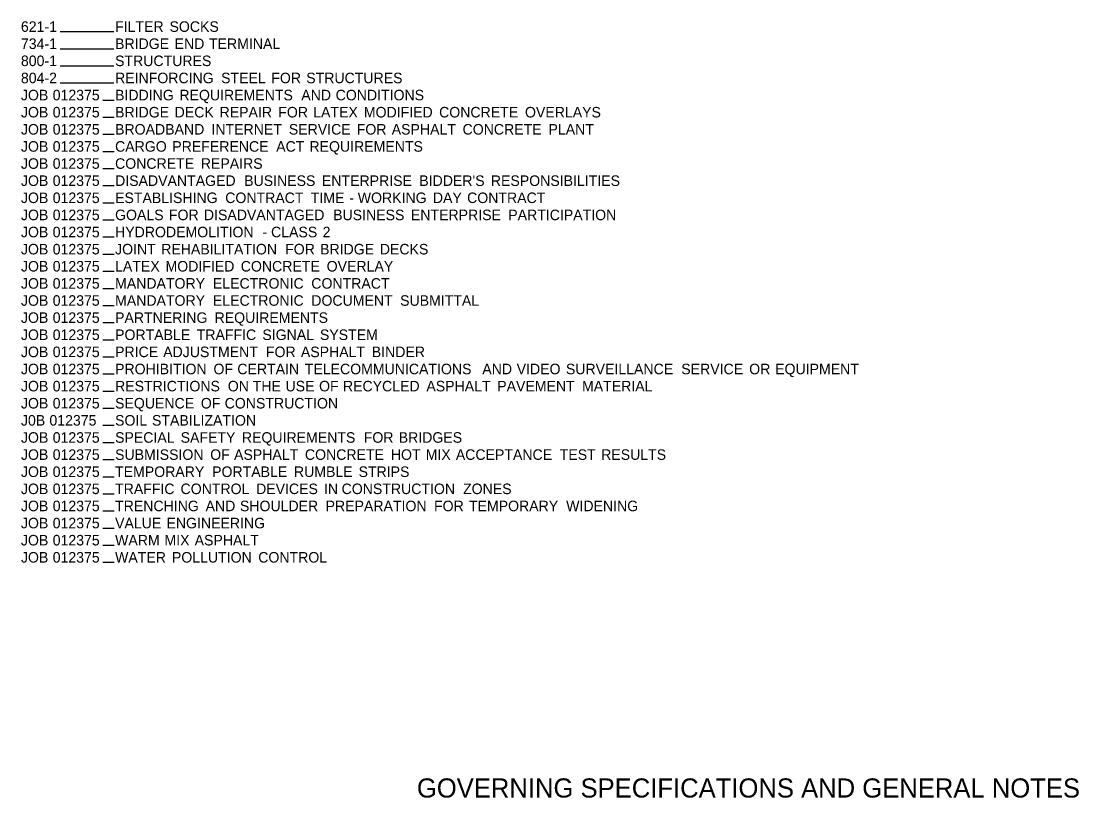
# Model space of a CAD drawing. Extents: x 1930579 to 1932220, y 596452 to 599479.
# Drawn here: x 1931525 to 1932188, y 598494 to 598981 of the extents above; entities that cross this region are included whole.
import ezdxf

# ---------------------------------------------------------------- set-up
doc = ezdxf.new("R2010")
doc.units = 0
doc.layers.add('Default', color=7, linetype='Continuous')
doc.layers.add('R_Border', color=7, linetype='Continuous')

msp = doc.modelspace()

# ---------------------------------------------------------------- linework, layer by layer
at = {"layer": 'R_Border'}
for p, q in [((1931549.9, 598974.32), (1931583.53, 598974.32)), ((1931549.9, 598963.59), (1931583.53, 598963.59)), ((1931549.9, 598952.87), (1931583.53, 598952.87)), ((1931549.9, 598942.14), (1931583.53, 598942.14)), ((1931576.59, 598931.42), (1931583.8, 598931.42)), ((1931576.59, 598920.69), (1931583.8, 598920.69)), ((1931576.59, 598909.97), (1931583.8, 598909.97)), ((1931576.59, 598899.24), (1931583.8, 598899.24)), ((1931576.59, 598888.52), (1931583.8, 598888.52)), ((1931576.59, 598877.79), (1931583.8, 598877.79)), ((1931576.59, 598867.07), (1931583.8, 598867.07)), ((1931576.59, 598856.34), (1931583.8, 598856.34)), ((1931576.59, 598845.62), (1931583.8, 598845.62)), ((1931576.59, 598834.89), (1931583.8, 598834.89)), ((1931576.59, 598824.17), (1931583.8, 598824.17)), ((1931576.59, 598813.44), (1931583.8, 598813.44)), ((1931576.59, 598802.72), (1931583.8, 598802.72)), ((1931576.59, 598791.99), (1931583.8, 598791.99)), ((1931576.59, 598781.27), (1931583.8, 598781.27)), ((1931576.59, 598770.54), (1931583.8, 598770.54)), ((1931576.59, 598759.82), (1931583.8, 598759.82)), ((1931576.59, 598749.09), (1931583.8, 598749.09)), ((1931576.59, 598738.37), (1931583.8, 598738.37)), ((1931576.59, 598727.64), (1931583.8, 598727.64)), ((1931576.59, 598716.92), (1931583.8, 598716.92)), ((1931576.59, 598706.19), (1931583.8, 598706.19)), ((1931576.59, 598695.47), (1931583.8, 598695.47)), ((1931576.59, 598684.74), (1931583.8, 598684.74)), ((1931576.59, 598674.02), (1931583.8, 598674.02)), ((1931576.59, 598663.29), (1931583.8, 598663.29)), ((1931576.59, 598652.57), (1931583.8, 598652.57)), ((1931576.59, 598641.84), (1931583.8, 598641.84))]:
    msp.add_line(p, q, dxfattribs=at)

# ---------------------------------------------------------------- texts
at = {"layer": 'Default'}
for s, p in [('621-1', (1931525.34, 598974.13)), ('FILTER', (1931584.33, 598974.13)), (' SOCKS', (1931615.97, 598974.13)), ('734-1', (1931525.34, 598963.4)), ('BRIDGE', (1931584.33, 598963.4)), (' END', (1931619.19, 598963.4)), (' TERMINAL', (1931640.73, 598963.4)), ('800-1', (1931525.34, 598952.68)), ('STRUCTURES', (1931584.33, 598952.68)), ('804-2', (1931525.34, 598941.95)), ('REINFORCING', (1931584.33, 598941.95)), (' STEEL', (1931648.3, 598941.95)), (' FOR', (1931679.76, 598941.95)), (' STRUCTURES', (1931701.66, 598941.95)), ('JOB', (1931525.34, 598931.23)), (' 012375', (1931542.79, 598931.23)), ('BIDDING', (1931584.33, 598931.23)), (' REQUIREMENTS', (1931622.18, 598931.23)), (' AND', (1931698.55, 598931.23)), (' CONDITIONS', (1931720.09, 598931.23)), ('JOB', (1931525.34, 598920.5)), (' 012375', (1931542.79, 598920.5)), ('BRIDGE', (1931584.33, 598920.5)), (' DECK', (1931619.19, 598920.5)), (' REPAIR', (1931647.36, 598920.5)), (' FOR', (1931684.13, 598920.5)), (' LATEX', (1931706.03, 598920.5)), (' MODIFIED', (1931737.75, 598920.5)), (' CONCRETE', (1931784.9, 598920.5)), (' OVERLAYS', (1931838.72, 598920.5)), ('JOB', (1931525.34, 598909.78)), (' 012375', (1931542.79, 598909.78)), ('BROADBAND', (1931584.33, 598909.78)), (' INTERNET', (1931642.26, 598909.78)), (' SERVICE', (1931690.75, 598909.78)), (' FOR', (1931733.3, 598909.78)), (' ASPHALT', (1931755.21, 598909.78)), (' CONCRETE', (1931799.61, 598909.78)), (' PLANT', (1931853.43, 598909.78)), ('JOB', (1931525.34, 598899.05)), (' 012375', (1931542.79, 598899.05)), ('CARGO', (1931584.33, 598899.05)), (' PREFERENCE', (1931617.73, 598899.05)), (' ACT', (1931682.84, 598899.05)), (' REQUIREMENTS', (1931703.66, 598899.05)), ('JOB', (1931525.34, 598888.33)), (' 012375', (1931542.79, 598888.33)), ('CONCRETE', (1931584.33, 598888.33)), (' REPAIRS', (1931635.59, 598888.33)), ('JOB', (1931525.34, 598877.6)), (' 012375', (1931542.79, 598877.6)), ('DISADVANTAGED', (1931584.33, 598877.6)), (' BUSINESS', (1931662.76, 598877.6)), (' ENTERPRISE', (1931711.48, 598877.6)), (" BIDDER'S", (1931772.48, 598877.6)), (' RESPONSIBILITIES', (1931817.32, 598877.6)), ('JOB', (1931525.34, 598866.88)), (' 012375', (1931542.79, 598866.88)), ('ESTABLISHING', (1931584.33, 598866.88)), (' CONTRACT', (1931650.89, 598866.88)), (' TIME', (1931704.5, 598866.88)), (' WORKING', (1931733.93, 598866.88)), (' DAY', (1931781, 598866.88)), (' CONTRACT', (1931802.45, 598866.88)), (' -', (1931728.59, 598866.88)), ('JOB', (1931525.34, 598856.15)), (' 012375', (1931542.79, 598856.15)), ('GOALS', (1931584.33, 598856.15)), (' FOR', (1931615.62, 598856.15)), (' DISADVANTAGED', (1931637.52, 598856.15)), (' BUSINESS', (1931718.52, 598856.15)), (' ENTERPRISE', (1931767.24, 598856.15)), (' PARTICIPATION', (1931828.24, 598856.15)), ('JOB', (1931525.34, 598845.43)), (' 012375', (1931542.79, 598845.43)), ('HYDRODEMOLITION', (1931584.33, 598845.43)), (' CLASS', (1931679.6, 598845.43)), (' 2', (1931711.93, 598845.43)), (' -', (1931674.26, 598845.43)), ('JOB', (1931525.34, 598834.7)), (' 012375', (1931542.79, 598834.7)), ('JOINT', (1931584.33, 598834.7)), (' REHABILITATION', (1931610.78, 598834.7)), (' FOR', (1931688.43, 598834.7)), (' BRIDGE', (1931710.33, 598834.7)), (' DECKS', (1931747.76, 598834.7)), ('JOB', (1931525.34, 598823.98)), (' 012375', (1931542.79, 598823.98)), ('LATEX', (1931584.33, 598823.98)), (' MODIFIED', (1931613.48, 598823.98)), (' CONCRETE', (1931660.63, 598823.98)), (' OVERLAY', (1931714.46, 598823.98)), ('JOB', (1931525.34, 598813.25)), (' 012375', (1931542.79, 598813.25)), ('MANDATORY', (1931584.33, 598813.25)), (' ELECTRONIC', (1931643.18, 598813.25)), (' CONTRACT', (1931704.82, 598813.25)), ('JOB', (1931525.34, 598802.53)), (' 012375', (1931542.79, 598802.53)), ('MANDATORY', (1931584.33, 598802.53)), (' ELECTRONIC', (1931643.18, 598802.53)), (' DOCUMENT', (1931704.82, 598802.53)), (' SUBMITTAL', (1931760.47, 598802.53)), ('JOB', (1931525.34, 598791.8)), (' 012375', (1931542.79, 598791.8)), ('PARTNERING', (1931584.33, 598791.8)), (' REQUIREMENTS', (1931644.21, 598791.8)), ('JOB', (1931525.34, 598781.08)), (' 012375', (1931542.79, 598781.08)), ('PORTABLE', (1931584.33, 598781.08)), (' TRAFFIC', (1931633.04, 598781.08)), (' SIGNAL', (1931674.17, 598781.08)), (' SYSTEM', (1931710.22, 598781.08)), ('JOB', (1931525.34, 598770.35)), (' 012375', (1931542.79, 598770.35)), ('PRICE', (1931584.33, 598770.35)), (' ADJUSTMENT', (1931612.02, 598770.35)), (' FOR', (1931676.39, 598770.35)), (' ASPHALT', (1931698.3, 598770.35)), (' BINDER', (1931742.7, 598770.35)), ('JOB', (1931525.34, 598759.63)), (' 012375', (1931542.79, 598759.63)), ('PROHIBITION', (1931584.33, 598759.63)), (' OF', (1931643.52, 598759.63)), (' CERTAIN', (1931658.47, 598759.63)), (' TELECOMMUNICATIONS', (1931700.75, 598759.63)), (' AND', (1931811.97, 598759.63)), (' VIDEO', (1931833.51, 598759.63)), (' SURVEILLANCE', (1931864.35, 598759.63)), (' SERVICE', (1931936.64, 598759.63)), (' OR', (1931979.19, 598759.63)), (' EQUIPMENT', (1931995.46, 598759.63)), ('JOB', (1931525.34, 598748.9)), (' 012375', (1931542.79, 598748.9)), ('RESTRICTIONS', (1931584.33, 598748.9)), (' ON', (1931652.51, 598748.9)), (' THE', (1931668.14, 598748.9)), (' USE', (1931688.66, 598748.9)), (' OF', (1931709.69, 598748.9)), (' RECYCLED', (1931724.64, 598748.9)), (' ASPHALT', (1931776.93, 598748.9)), (' PAVEMENT', (1931821.33, 598748.9)), (' MATERIAL', (1931874.45, 598748.9)), ('JOB', (1931525.34, 598738.18)), (' 012375', (1931542.79, 598738.18)), ('SEQUENCE', (1931584.33, 598738.18)), (' OF', (1931635.6, 598738.18)), (' CONSTRUCTION', (1931650.54, 598738.18)), ('J0B', (1931525.34, 598727.45)), (' 012375', (1931540.74, 598727.45)), ('SOIL', (1931584.33, 598727.45)), (' STABILIZATION', (1931605.01, 598727.45)), ('JOB', (1931525.34, 598716.73)), (' 012375', (1931542.79, 598716.73)), ('SPECIAL', (1931584.33, 598716.73)), (' SAFETY', (1931622.96, 598716.73)), (' REQUIREMENTS', (1931661.32, 598716.73)), (' FOR', (1931737.7, 598716.73)), (' BRIDGES', (1931759.6, 598716.73)), ('JOB', (1931525.34, 598706)), (' 012375', (1931542.79, 598706)), ('SUBMISSION', (1931584.33, 598706)), (' OF', (1931641.48, 598706)), (' ASPHALT', (1931656.42, 598706)), (' CONCRETE', (1931700.83, 598706)), (' HOT', (1931754.65, 598706)), (' MIX', (1931776.49, 598706)), (' ACCEPTANCE', (1931795.39, 598706)), (' TEST', (1931860.49, 598706)), (' RESULTS', (1931886.44, 598706)), ('JOB', (1931525.34, 598695.28)), (' 012375', (1931542.79, 598695.28)), ('TEMPORARY', (1931584.33, 598695.28)), (' PORTABLE', (1931642.68, 598695.28)), (' RUMBLE', (1931693.95, 598695.28)), (' STRIPS', (1931734.45, 598695.28)), ('JOB', (1931525.34, 598684.55)), (' 012375', (1931542.79, 598684.55)), ('TRAFFIC', (1931584.33, 598684.55)), (' CONTROL', (1931622.9, 598684.55)), (' DEVICES', (1931670.22, 598684.55)), (' IN', (1931712.79, 598684.55)), (' CONSTRUCTION', (1931723.81, 598684.55)), (' ZONES', (1931799.91, 598684.55)), ('JOB', (1931525.34, 598673.83)), (' 012375', (1931542.79, 598673.83)), ('TRENCHING', (1931584.33, 598673.83)), (' AND', (1931638.57, 598673.83)), (' SHOULDER', (1931660.11, 598673.83)), (' PREPARATION', (1931713.79, 598673.83)), (' FOR', (1931781.71, 598673.83)), (' TEMPORARY', (1931803.61, 598673.83)), (' WIDENING', (1931864.52, 598673.83)), ('JOB', (1931525.34, 598663.1)), (' 012375', (1931542.79, 598663.1)), ('VALUE', (1931584.33, 598663.1)), (' ENGINEERING', (1931614.08, 598663.1)), ('JOB', (1931525.34, 598652.38)), (' 012375', (1931542.79, 598652.38)), ('WARM', (1931584.33, 598652.38)), (' MIX', (1931612.83, 598652.38)), (' ASPHALT', (1931631.72, 598652.38)), ('JOB', (1931525.34, 598641.65)), (' 012375', (1931542.79, 598641.65)), ('WATER', (1931584.33, 598641.65)), (' POLLUTION', (1931617.5, 598641.65)), (' CONTROL', (1931671.58, 598641.65))]:
    msp.add_text(s, height=6.6, dxfattribs=at).set_placement(p)
at = {"layer": 'R_Border'}
msp.add_text('GOVERNING SPECIFICATIONS AND GENERAL NOTES ', height=12, rotation=360, dxfattribs=at).set_placement((1931773.43, 598494.45))

doc.saveas('drawing.dxf')
